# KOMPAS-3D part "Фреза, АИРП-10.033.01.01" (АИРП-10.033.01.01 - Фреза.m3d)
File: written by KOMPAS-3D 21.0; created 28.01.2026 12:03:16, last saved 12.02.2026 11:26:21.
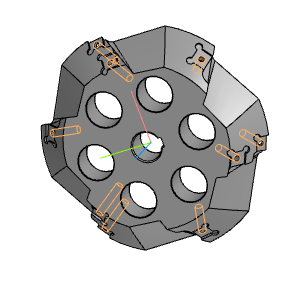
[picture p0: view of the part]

Document properties: Автор: Rushan; Полное имя файла: C:\Users\DMitkin\Music\АИРП-10.033.01.01 - Фреза.m3d

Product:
- Part/product: Фреза  | designation АИРП-10.033.01.01
    Материал: Д16 ГОСТ 4784-2019 (density 2770 kg/m3)
    Масса: 1.033703
    Форматы листов документа: A2

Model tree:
1. Эскиз:1
2. Элемент вращения:1
     Угол 1 = 360
3. Эскиз:2  (with: Элемент вращения:1)
4. Элемент выдавливания:1
     Расстояние 2 = 25.2
5. Эскиз:3  (with: Элемент вращения:1)
6. Элемент выдавливания:2
     Расстояние 2 = 25.2
7. Эскиз:4  (with: Элемент вращения:1, Элемент выдавливания:1)
8. Эскиз:5  (with: Элемент вращения:1)
9. Элемент по сечениям:2
     Толщина стенки 1 = 0.2; Толщина стенки 2 = 3
10. Массив по концентрической сетке:2  (with: Элемент по сечениям:2)  (6 pattern instances)
     Шаг 2 = 360
11. Фаска:1  (with: Элемент выдавливания:2)
     Угол = 45; Длина 1 = 0.5; Длина 2 = 0.5
12. Скругление:1  (with: Элемент выдавливания:1)
     Радиус = 1
13. Касательная плоскость:1  (with: Элемент вращения:1)
     Угол = 60
14. Эскиз:10  (with: Элемент по сечениям:2)
15. Удалить грани:3  (with: Элемент по сечениям:2)
16. Удалить грани:4  (with: Элемент по сечениям:2)
17. Эскиз:11  (with: Элемент по сечениям:2)
18. Плоскость, касательная в точке:1  (with: Элемент вращения:1, Элемент по сечениям:2)
19. Эскиз:12
20. Элемент выдавливания:6
     Толщина стенки 2 = 2; Расстояние 1 = 7
21. Удалить грани:5  (with: Элемент выдавливания:6)
22. Массив по концентрической сетке:3  (with: Элемент выдавливания:6)  (3 pattern instances)
     Шаг 2 = 360
23. Удалить грани:6  (with: Элемент выдавливания:6)
24. Плоскость, касательная в точке:5  (with: Элемент вращения:1, Элемент по сечениям:2)
25. Эскиз:14  (with: Элемент по сечениям:2)
26. Элемент выдавливания:7
     Расстояние 2 = 4
27. Массив по концентрической сетке:4  (with: Элемент выдавливания:7)  (3 pattern instances)
     Шаг 2 = 360
28. Плоскость, касательная в точке:6  (with: Элемент вращения:1, Элемент выдавливания:7)
29. Эскиз:15  (with: Элемент выдавливания:7)
30. Элемент выдавливания:8
     Расстояние 2 = 2
31. Отверстие:1  (with: Элемент выдавливания:8)  (labels: M6)
     Глубина выреза = 40; Диаметр отверстия = 4.91747; Угол конуса дна = 118; Расстояние 1 = -4.72504; Расстояние 2 = 6.10522
32. M6  (with: Элемент выдавливания:8, Элемент вращения:1)  (labels: cil0_24705-2004 coarse)
     Длина резьбы = 30; Шаг резьбы = 1; Номинальный диаметр резьбы = 6
33. Отверстие:2  (with: Элемент выдавливания:8, M6)  (labels: M6; cil0_24705-2004 coarse)
     Глубина выреза = 9; Диаметр отверстия = 4.91747; Угол конуса дна = 118; Расстояние 1 = -6; Расстояние 2 = 7; Длина резьбы = 30; Шаг резьбы = 1; Номинальный диаметр резьбы = 6
34. Массив по концентрической сетке:5  (with: Элемент выдавливания:8)  (3 pattern instances)
     Шаг 2 = 360
35. Массив по концентрической сетке:6  (with: Отверстие:1)  (labels: M6)  (2 pattern instances)
36. Отверстие:2  (labels: M6)
37. Отверстие:1  (labels: M6)
38. Отверстие:2  (labels: M6)
39. Эскиз:16  (with: Элемент выдавливания:6)
40. Элемент выдавливания:10
     Расстояние 2 = 2
41. Отверстие:3  (with: Элемент выдавливания:10, M6)  (labels: M6; cil0_24705-2004 coarse)
     Глубина выреза = 9; Диаметр отверстия = 4.91747; Угол конуса дна = 118; Расстояние 1 = -6; Расстояние 2 = 7; Длина резьбы = 24; Шаг резьбы = 1; Номинальный диаметр резьбы = 6
42. Массив по концентрической сетке:7  (with: Элемент выдавливания:10)  (3 pattern instances)
     Шаг 2 = 360
43. Массив по концентрической сетке:8  (with: Отверстие:3)  (labels: M6)  (2 pattern instances)
44. Отверстие:3  (labels: M6)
